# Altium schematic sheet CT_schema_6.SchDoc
size 282 x 251 mm
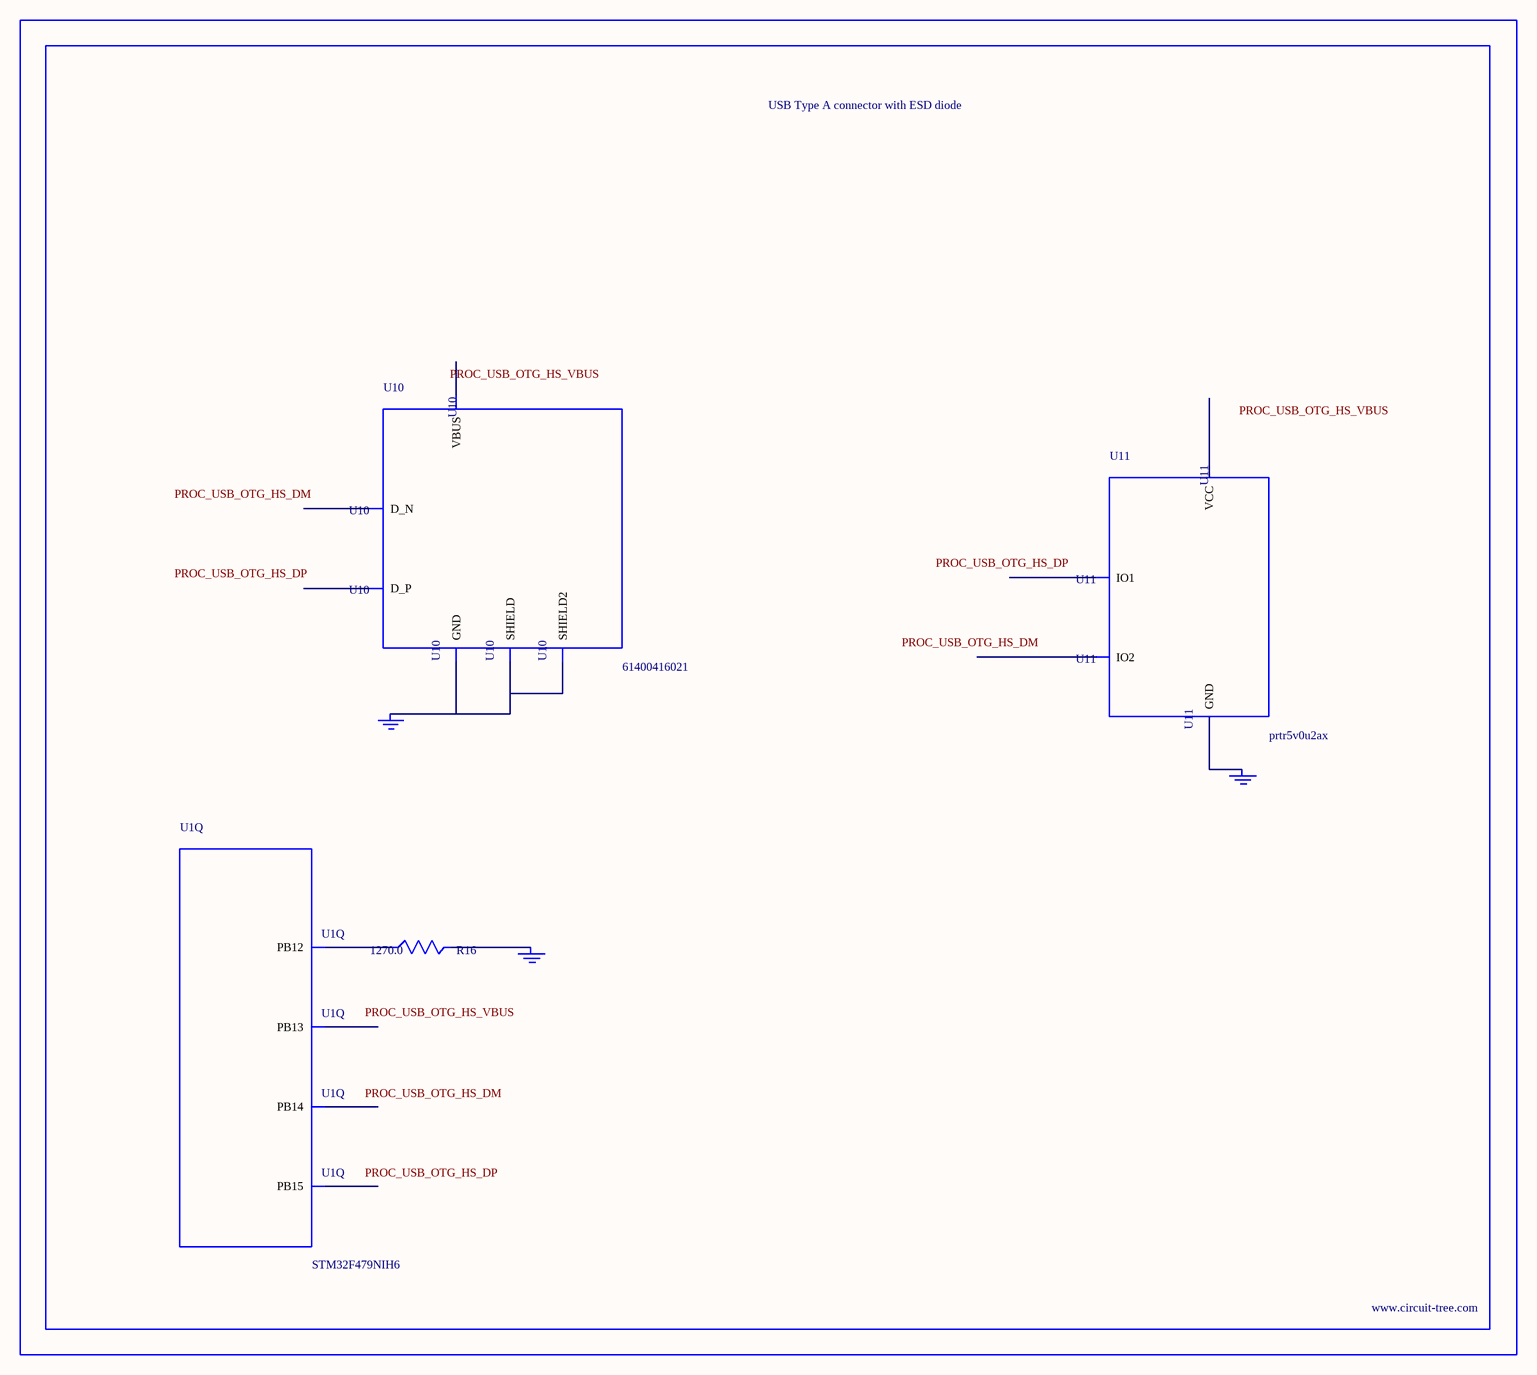
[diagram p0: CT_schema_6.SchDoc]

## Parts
BORDER5  (no value)
GND_INSTANCE_5_0  (no value)
GND_INSTANCE_5_1  (no value)
GND_INSTANCE_5_2  (no value)
R16  1270.0  [R0603]
U1  STM32F479NIH6  [TFBGA216]  (part Q of 17)
U10  61400416021  [USB-A-H]
U11  prtr5v0u2ax  [SOT143B]

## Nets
NetGND_INSTANCE_5_0_0: GND_INSTANCE_5_0.0(GND) U10.4(GND) U10.5(SHIELD) U10.6(SHIELD2)
NetGND_INSTANCE_5_1_0: GND_INSTANCE_5_1.0(GND) R16.2
NetGND_INSTANCE_5_2_0: GND_INSTANCE_5_2.0(GND) U11.1(GND)
NetR16_1: R16.1 U1.L13(PB12)

Not connected (* = marked no-connect by the designer): U1 K14(PB13) R14(PB14) R15(PB15); U10 1(VBUS) 2(D_N) 3(D_P); U11 2(IO1) 3(IO2) 4(VCC)

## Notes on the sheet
- Labels drawn without touching a wire or pin: PROC_USB_OTG_HS_DM, PROC_USB_OTG_HS_DP, PROC_USB_OTG_HS_VBUS

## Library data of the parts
BORDER5 = BORDER_PAGE5
GND_INSTANCE_5_0-GND_INSTANCE_5_2 = GND
R16 = RC0603FR-071K27L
